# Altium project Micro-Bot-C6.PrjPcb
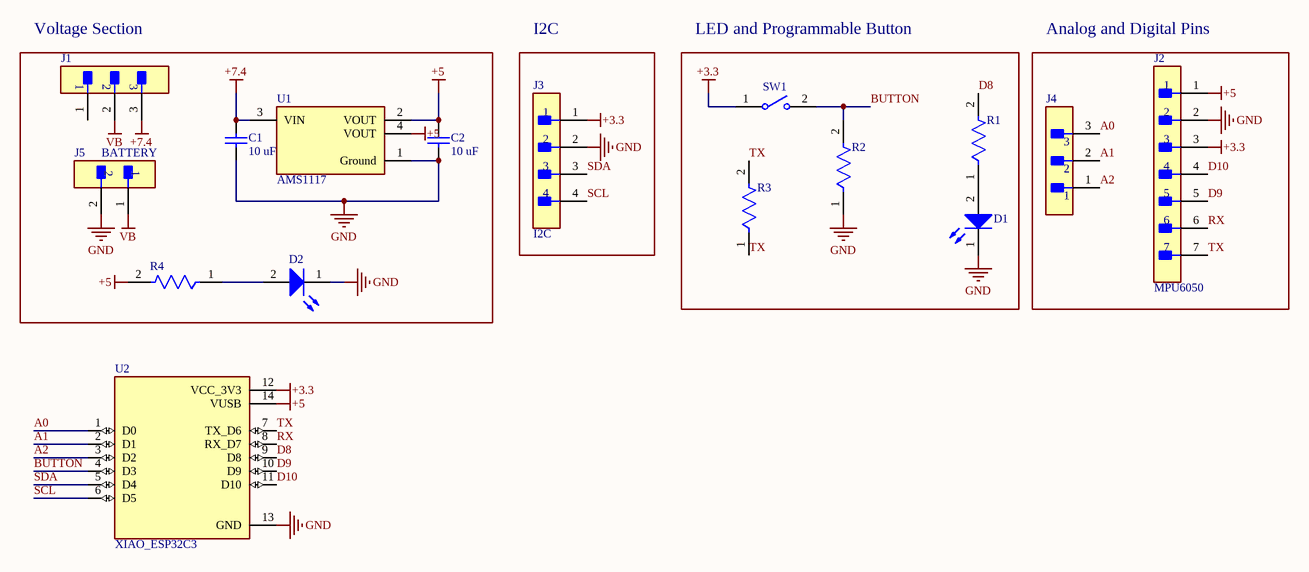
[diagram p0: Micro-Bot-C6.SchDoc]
1 sheet, 16 parts. Net scope: global (net labels, ports and power ports of the same name join across sheets).
Board file: Micro-Bot-C6.PcbDoc

## Sheet Micro-Bot-C6.SchDoc
size A4; SheetNumber: 1; SheetTotal: 1

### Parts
C1  10 uF  [CAPC1206(3216)100_M]
C2  10 uF  [CAPC1206(3216)100_M]
D1  (no value)  [WL-SMCW_1206_150120xx75000]
D2  (no value)  [WL-SMCW_1206_150120xx75000]
J1  (no value)  [FP-22-28-4030-MFG]
J2  MPU6050  [FP-TSW-107-07-G-S-MFG]
J3  I2C  [FP-TSW-104-23-T-S-MFG]
J4  (no value)  [FP-22-28-4030-MFG]
J5  BATTERY  [FP-TSW-102-14-G-S-MFG]
R1  (no value)  [FP-RC1206-MFG]
R2  (no value)  [FP-RC1206-MFG]
R3  (no value)  [FP-RC1206-MFG]
R4  (no value)  [FP-RC1206-MFG]
SW1  (no value)  [434111043826]
U1  AMS1117  [FP-AMS1117-IPC_A]
U2  XIAO_ESP32C3  [MODULE_XIAO_ESP32C3]

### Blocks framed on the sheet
Voltage Section: C1 C2 D2 J1 J5 R4 U1
I2C: J3
LED and Programmable Button: D1 R1-R3 SW1
Analog and Digital Pins: J2 J4

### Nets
+3.3: J2.3 J3.1 SW1.1 U2.12(VCC_3V3)
+5: C2.2 J2.1 R4.2 U1.2(VOUT) U1.4(VOUT) U2.14(VUSB)
+7.4: C1.2 J1.3 U1.3(VIN)
GND: C1.1 C2.1 D1.1(K) D2.1(K) J2.2 J3.2 J5.2 R2.1 U1.1(Ground) U2.13(GND)
VB: J1.2 J5.1
A0: J4.3 U2.1(D0)
A1: J4.2 U2.2(D1)
A2: J4.1 U2.3(D2)
BUTTON: R2.2 SW1.2 U2.4(D3)
D8: R1.2 U2.9(D8)
D9: J2.5 U2.10(D9)
D10: J2.4 U2.11(D10)
RX: J2.6 U2.8(RX_D7)
SCL: J3.4 U2.6(D5)
SDA: J3.3 U2.5(D4)
TX: J2.7 R3.1 R3.2 U2.7(TX_D6)
NetD1_2: D1.2(A) R1.1
NetD2_2: D2.2(A) R4.1

Not connected (* = marked no-connect by the designer): J1 1

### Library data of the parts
C1 C2 = CMP-1037-00368-1: CAP 4.7pF 10V ±0.25pF 1206 (3216 Metric) Thickness 1mm SMD; Case-EIA: 1206; Case-Metric: 3216; Tolerance: Â±0.25pF
D1 D2 = CMP-1426-00015-3: WL-SMCW SMT Mono-Color Chip LED Waterclear; Manufacturer Package Identifier: LED_1206; Dominant Wavelength: 470nm; Lens Style: Clear, Rectangular; Test Current: 20mA; Forward Voltage: 3.2V; Forward Current: 100mA; Peak Wavelength: 465nm; Max Reverse Voltage (DC): 5V; Viewing Angle: 140°; Color: Blue; Luminous Intensity: 145mcd
J1 J4 = CMP-04776-000098-1: CONN HEADER VERT 3POS 2.54MM; Manufacturer: Molex; Conn Orientation: Vertical; Conn Gender: Male; Current Rating: 4A; Voltage Rating: 500V; Number Of Contacts: 3
J2 = CMP-02766-000065-1: CONN HEADER VERT 7POS 2.54MM; Manufacturer Part Number: TSW-107-07-G-S; Manufacturer: SAMTEC; Conn Orientation: Straight; Number Of Contacts: 7; Conn Gender: Male
J3 = CMP-02766-001388-1: CONN HEADER VERT 4POS 2.54MM; Number of Contacts: 4; Gender: Male; Connector Type: Male Pin; Max Voltage Rating (AC): 550V; Max Current Rating: 7.6A
J5 = CMP-02766-001740-1: CONN HEADER VERT 2POS 2.54MM; Number of Positions: 2; Max Current Rating: 7.6A; Gender: Male; Max Voltage Rating (AC): 550V
R1-R4 = CMP-2100-03681-2: RES SMD 0 OHM JUMPER 1/4W 1206; Manufacturer Part Number: RC1206JR-070RL; Manufacturer: YAGEO; Voltage Rating: 200V; Temperature Coefficient: 300ppm/°C; Power Rating: 0.25W; Value: 0Ω; Tolerance: 5%
SW1 = CMP-1459-00002-3: Rectangular Button WS-TASV White Surface Mount Tactile Switch 4.30mm 50mA 0.05A @ 12VDC 260gf; Operating Force: 260N; Contact Resistance: 100mΩ; Voltage Rating: 12V
U1 = CMP-209535-000001-1: LDO Voltage Regulators 1A, 3.3V; Manufacturer Part Number: AMS1117-3.3; Manufacturer: Advanced Monolithic Systems; Dropout Voltage: 1.1V; Output Type: Fixed; Nominal Supply Current: 5mA; Max Power Dissipation: 1.2W; Max Supply Voltage: 15V; Number Of Outputs: 1; Standoff Height: 0.64mm; Max Junction Temp: +125°C
U2 = XIAO_ESP32C3: Dev.kit: evaluation; u.FL antenna,prototype board; XIAO; PIN: 2x7; MF: Seeed Studio; MP: XIAO ESP32C3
